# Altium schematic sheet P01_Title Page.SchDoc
size 386 x 246 mm
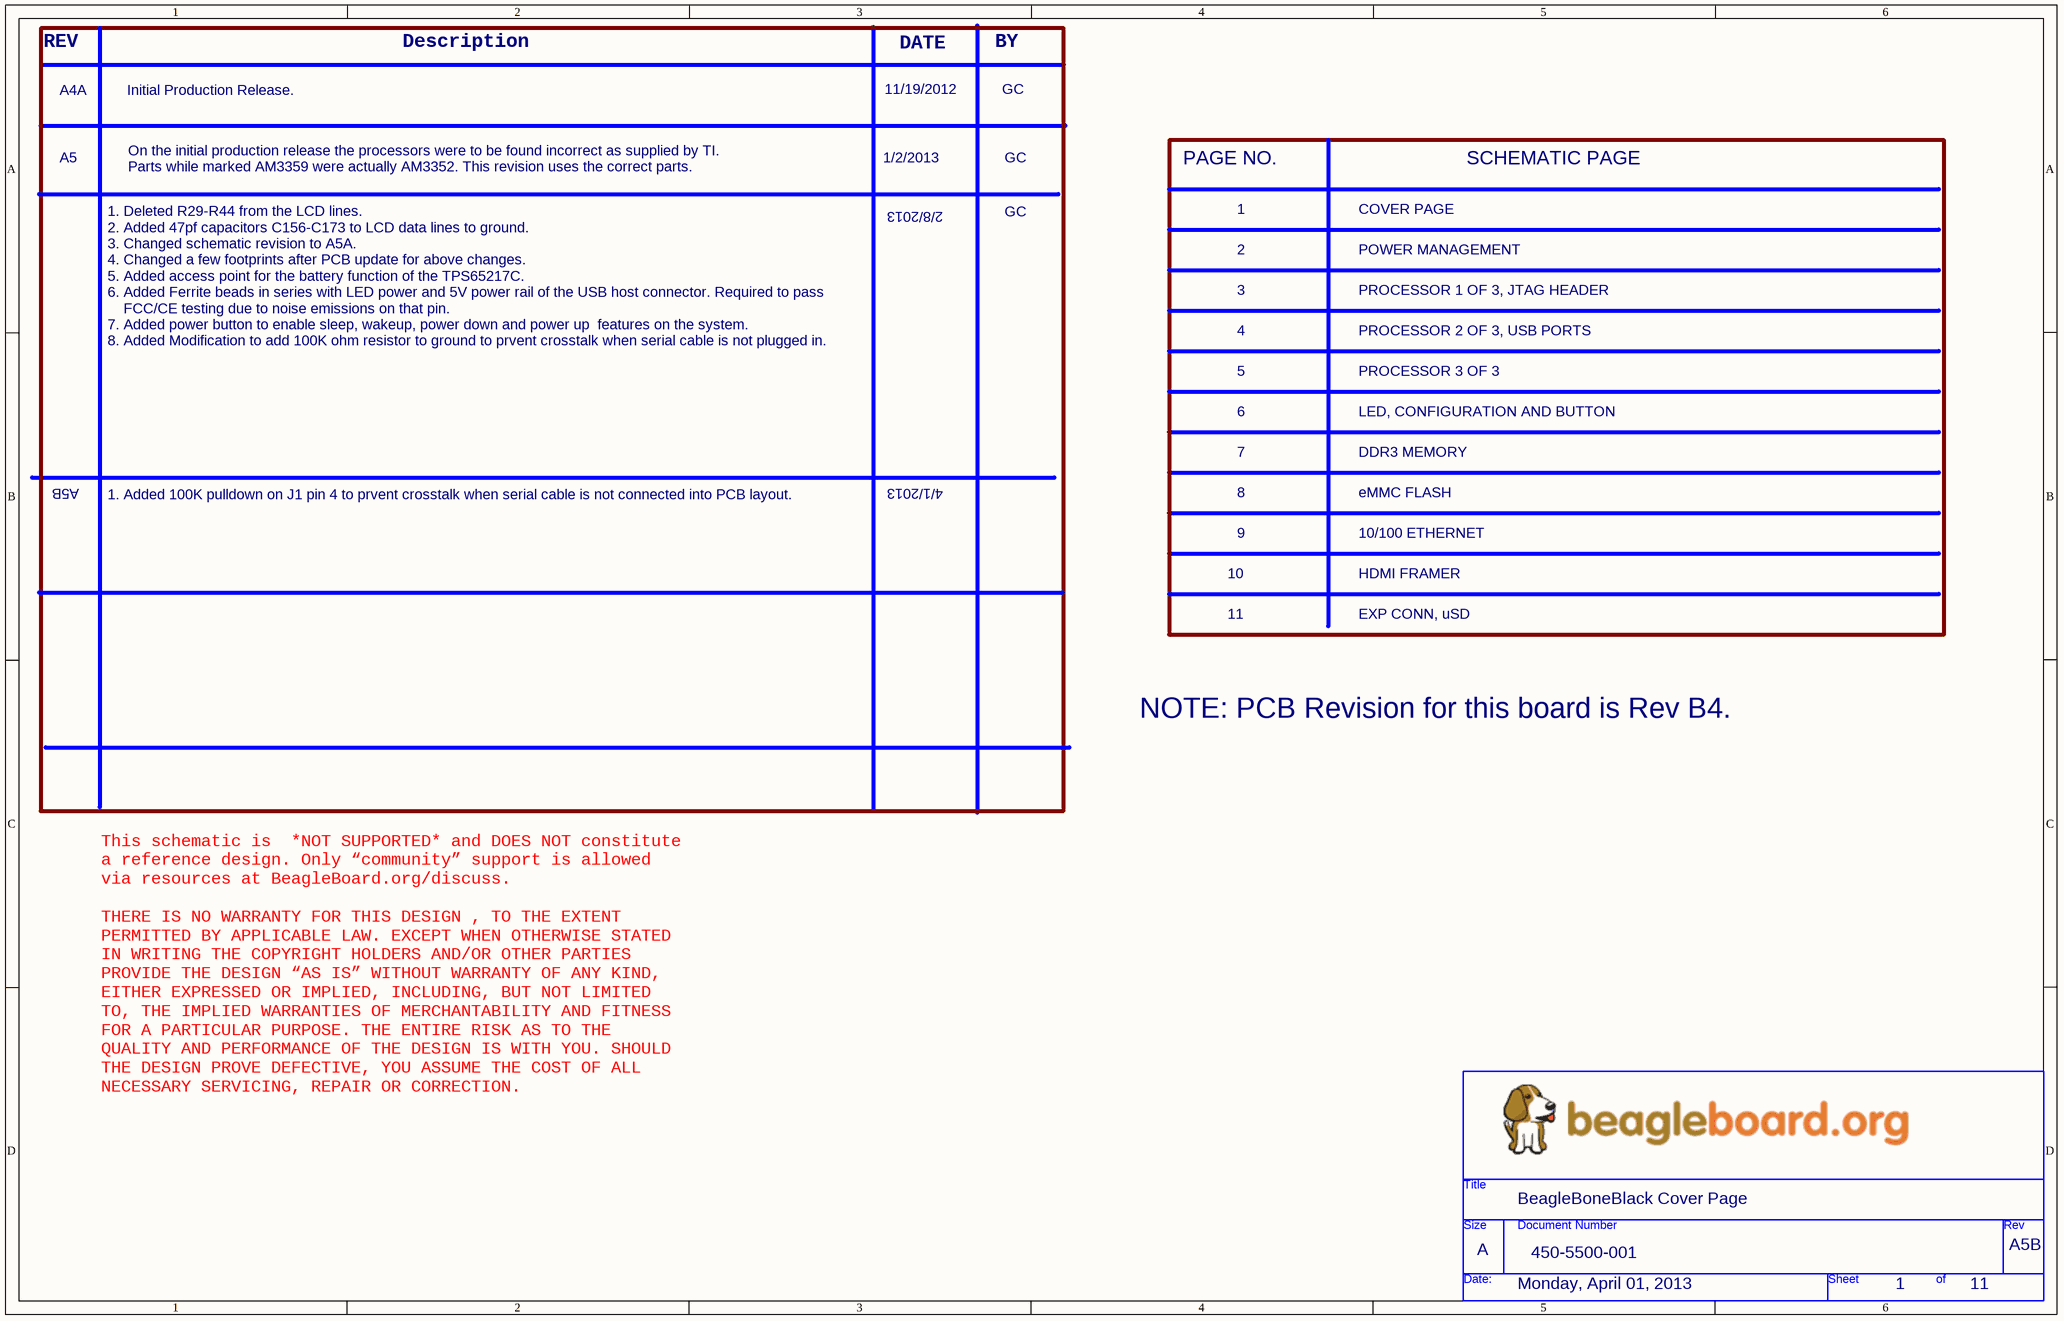
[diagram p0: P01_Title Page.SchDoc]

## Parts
*  Page Create Date: Monday, April 01, 2013  Doc: 450-5500-001  RevCode: A5B  Title: BeagleBoneBlack Cover Page  Page Size: A  Page Number: 1  Page Count: 11  (hidden comment: BeagleBoard_org)  (graphical)

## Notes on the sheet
- REV
- Description
- DATE
- BY
- A4A
- Initial Production Release.
- 11/19/2012
- GC
- A5
- On the initial production release the processors were to be found incorrect as supplied by TI.
  Parts while marked AM3359 were actually AM3352. This revision uses the correct parts.
- 1/2/2013
- PAGE NO.
- SCHEMATIC PAGE
- 2/8/2013
- 1
- 2
- POWER MANAGEMENT
- COVER PAGE
- 3
- PROCESSOR 1 OF 3, JTAG HEADER
- 4
- 5
- PROCESSOR 2 OF 3, USB PORTS
- PROCESSOR 3 OF 3
- 1. Deleted R29-R44 from the LCD lines.
  2. Added 47pf capacitors C156-C173 to LCD data lines to ground.
  3. Changed schematic revision to A5A.
  4. Changed a few footprints after PCB update for above changes.
  5. Added access point for the battery function of the TPS65217C.
  6. Added Ferrite beads in series with LED power and 5V power rail of the USB host connector. Required to pass
  FCC/CE testing due to noise emissions on that pin.
  7. Added power button to enable sleep, wakeup, power down and power up  features on the system.
  8. Added Modification to add 100K ohm resistor to ground to prvent crosstalk when serial cable is not plugged in.
- 7
- 6
- DDR3 MEMORY
- LED, CONFIGURATION AND BUTTON
- A5B
- 4/1/2013
- 8
- eMMC FLASH
- 1. Added 100K pulldown on J1 pin 4 to prvent crosstalk when serial cable is not connected into PCB layout.
- 10
- 9
- HDMI FRAMER
- 10/100 ETHERNET
- 11
- EXP CONN, uSD
- NOTE: PCB Revision for this board is Rev B4.
- This schematic is  *NOT SUPPORTED* and DOES NOT constitute
  a reference design. Only “community” support is allowed
  via resources at BeagleBoard.org/discuss.
  THERE IS NO WARRANTY FOR THIS DESIGN , TO THE EXTENT
  PERMITTED BY APPLICABLE LAW. EXCEPT WHEN OTHERWISE STATED
  IN WRITING THE COPYRIGHT HOLDERS AND/OR OTHER PARTIES
  PROVIDE THE DESIGN “AS IS” WITHOUT WARRANTY OF ANY KIND,
  EITHER EXPRESSED OR IMPLIED, INCLUDING, BUT NOT LIMITED
  TO, THE IMPLIED WARRANTIES OF MERCHANTABILITY AND FITNESS
  FOR A PARTICULAR PURPOSE. THE ENTIRE RISK AS TO THE
  QUALITY AND PERFORMANCE OF THE DESIGN IS WITH YOU. SHOULD
  THE DESIGN PROVE DEFECTIVE, YOU ASSUME THE COST OF ALL
  NECESSARY SERVICING, REPAIR OR CORRECTION.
